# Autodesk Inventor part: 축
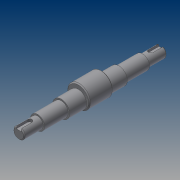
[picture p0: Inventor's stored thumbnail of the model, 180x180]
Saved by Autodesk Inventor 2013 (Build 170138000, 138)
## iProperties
Created: 2014-12
Part Number: 축
Material: Generic
Document SubType Name: Modeling
Designer: CAD-B27
Density: 1 g/cm^3
Author: CAD-B27
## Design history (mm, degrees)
sketch "스케치1"
  geometry: L1 (-75.5, 9)-(75.5, 9); L2 (75.5, 9)-(75.5, 0); L3 (75.5, 0)-(-75.5, 0); L4 (-75.5, 0)-(-75.5, 9); L5 (-75.5, 6)-(-55.5, 6); L6 (-55.5, 6)-(-55.5, 7.5); L7 (-55.5, 7.5)-(-30.5, 7.5); L8 (-30.5, 7.5)-(-30.5, 9); L9 (30.5, 9)-(30.5, 7.5); L10 (30.5, 7.5)-(55.5, 7.5); L11 (55.5, 7.5)-(55.5, 6); L12 (55.5, 6)-(75.5, 6); L13 (-12.5, 14)-(12.5, 14); L14 (12.5, 14)-(12.5, 2); L15 (12.5, 2)-(-12.5, 2); L16 (-12.5, 2)-(-12.5, 14); 2 further points
  constraints: 32 end point, 9 parallel, 5 perpendicular, 4 point on line, 2 horizontal, 2 horizontal alignment, 1 coincident, 1 midpoint
  dimensions: "d0" = 151 distance of L2.end L3.end; "d2" = 18 diameter of L1 L3; "d3" = 15 diameter of L7 L3; "d4" = 12 diameter of L5 L3; "d5" = 20 distance of L5.start L5.end; "d6" = 25 distance of L6.end L7.end; "d7" = 20 distance of L11.end L12.end; "d8" = 25 distance of L9.end L10.end; "d9" = 24 diameter of L13 L15; "d10" = 2 distance between parallel lines of L3 L15; "d11" = 18 distance between parallel lines of L16 L8; "d12" = 18 distance between parallel lines of L9 L14
revolve "회전1" stored, may be unused: angle "d13" = 90 deg
revolve "회전2" stored, may be unused: angle "d14" = 90 deg
node "작업 평면1"
sketch "스케치2"
  geometry: L1 (-4, 2.5)-(10, 2.5); L2 (10, 2.5)-(10, -2.5); L3 (10, -2.5)-(-4, -2.5); L4 (-4, -2.5)-(-4, 2.5); L5 (10, 6)-(10, -6) reference; 2 further points
  constraints: 8 end point, 2 midpoint, 2 parallel, 1 horizontal, 1 perpendicular
  dimensions: "d15" = 14 distance of L1.start L1.end; "d17" = 5 distance of L3.end L1.start
extrude "돌출1" cut sketch "스케치2" distance "d18" = 3; taper "d19" = 0 deg
fillet "모깎기1" dims "d20" = 2.5
chamfer "모따기1" distance "d21" = 1; stored, may be unused: second distance "d22" = 2, angle "d23" = 45 deg
node "솔리드1"
mirror "대칭1"
